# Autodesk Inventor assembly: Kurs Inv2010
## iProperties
Shininess: 64.0
Length Units: 11269
Angle Units: 11279
Time Units: 11290
Mass Units: 11283
Length Display Precision: 3
Angle Display Precision: 2
Compacted: True
Part Number: Kurs Inv2010
Document SubType Name: Assembly
Created: 2003-08
Designer: JWe
Manufacturer: Standard
Standards Organization: Custom
Density: 0.0
Volumn: 0.0
Area: 0.0
PropertySet Name: Model Information
Control State: 0
Master: False
Checked Out: False
Author: Administratör
